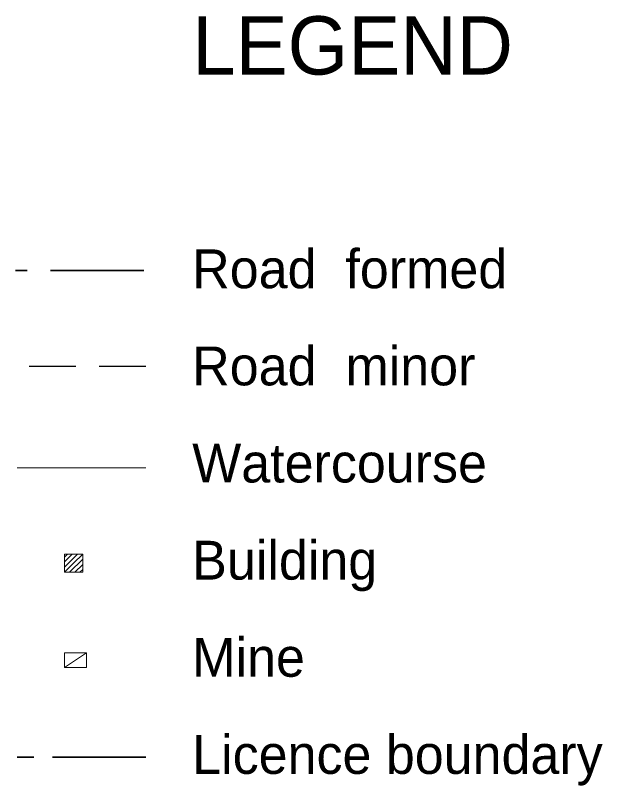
# Model space of a CAD drawing. Extents: x 796677 to 815278, y 8501144 to 8534586.
# Drawn here: x 805156 to 808176, y 8520330 to 8524294 of the extents above; entities that cross this region are included whole.
import ezdxf

# ---------------------------------------------------------------- set-up
doc = ezdxf.new("R2010")
doc.units = 0
doc.header["$LTSCALE"] = 80
for name, pattern in [('LONG_DASH_SHORT_DASH', [9.9, 6, -1.2, 1.5, -1.2]), ('LONG_DASHED', [7.5, 6, -1.5]), ('MEDIUM_DASHED', [4.5, 3, -1.5])]:
    doc.linetypes.add(name, pattern=pattern)
doc.layers.add('61', color=7, linetype='Continuous', lineweight=13)

msp = doc.modelspace()

# ---------------------------------------------------------------- linework, layer by layer
at = {"layer": '61', "linetype": 'LONG_DASHED', "lineweight": 35}
msp.add_line((805816.21, 8522981.27), (805155.51, 8522981.27), dxfattribs=at)
at = {"layer": '61', "linetype": 'MEDIUM_DASHED', "lineweight": 25}
msp.add_line((805825.52, 8522487.68), (805164.82, 8522487.68), dxfattribs=at)
at = {"layer": '61'}
for p, q in [((805825.52, 8521966.15), (805164.82, 8521966.15)), ((805475.37, 8521521.35), (805407.87, 8521453.85)), ((805447.87, 8521521.35), (805407.87, 8521481.35)), ((805422.87, 8521521.35), (805407.87, 8521506.35)), ((805501.62, 8521521.35), (805454.12, 8521473.85)), ((805407.87, 8521427.6), (805454.12, 8521473.85)), ((805501.62, 8521495.1), (805434.12, 8521427.6)), ((805501.62, 8521467.6), (805461.62, 8521427.6)), ((805501.62, 8521442.6), (805486.62, 8521427.6)), ((805521.28, 8521012.22), (805465.02, 8520974.72)), ((805408.78, 8520937.22), (805465.02, 8520974.72))]:
    msp.add_line(p, q, dxfattribs=at)
at = {"layer": '61', "linetype": 'LONG_DASH_SHORT_DASH', "lineweight": 35}
msp.add_line((805825.52, 8520476.07), (805164.82, 8520476.07), dxfattribs=at)
at = {"layer": '61'}
for points in [[(805501.62, 8521521.35), (805407.87, 8521521.35), (805407.87, 8521427.6), (805501.62, 8521427.6)], [(805408.78, 8520937.22), (805521.28, 8520937.22), (805521.28, 8521012.22), (805408.78, 8521012.22)]]:
    msp.add_lwpolyline(points, close=True, dxfattribs=at)

# ---------------------------------------------------------------- texts
for s, height, p in [('LEGEND', 300, (806064.8, 8523989.91)), ('Road  formed', 200, (806064.8, 8522889.91)), ('Road  minor', 200, (806064.8, 8522389.91)), ('Watercourse', 200, (806064.8, 8521889.91)), ('Building', 200, (806064.8, 8521389.91)), ('Mine', 200, (806064.8, 8520889.91)), ('Licence boundary', 200, (806064.8, 8520389.91))]:
    msp.add_text(s, height=height, dxfattribs=at).set_placement(p)

doc.saveas('drawing.dxf')
